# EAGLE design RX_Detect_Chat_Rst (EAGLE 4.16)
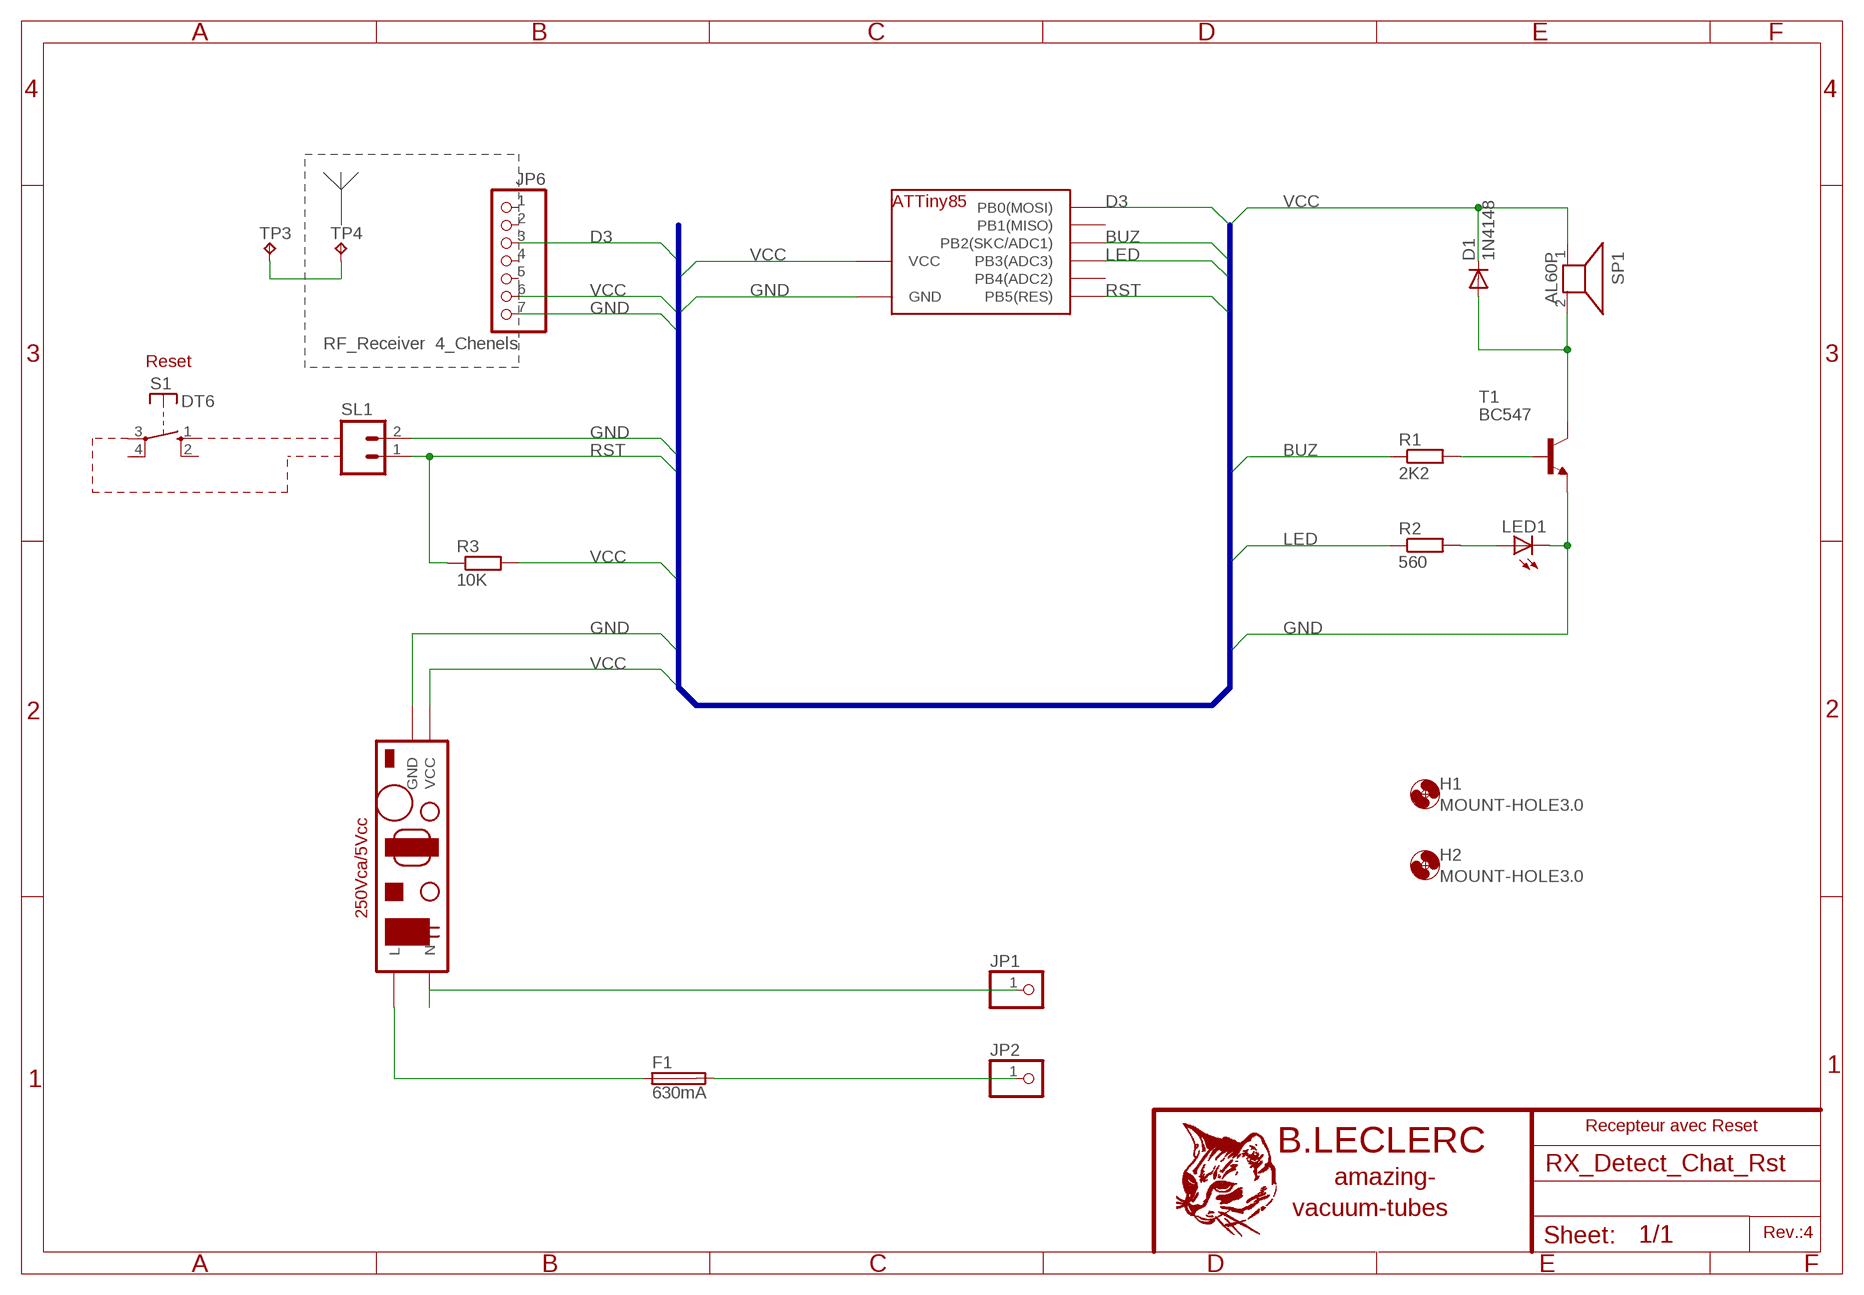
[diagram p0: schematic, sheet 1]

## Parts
D1  1N4148  DIODE-DO214BA  [DO214BA]
F1  630mA  FUSESHK20L  [SHK20L]
H1  MOUNT-HOLE3.0  [3,0]
H2  MOUNT-HOLE3.0  [3,0]
JP1  PINHD-1X1  [1X01]
JP2  PINHD-1X1  [1X01]
JP6  PINHD-1X7  [1X07]
LED1  LED5MM  [LED5MM]
R1  2K2  R-EU_M1206  [M1206]
R2  560  R-EU_M1206  [M1206]
R3  10K  R-EU_0207/10  [0207/10]
S1  DT6  [DT6]
SL1  M02  [02P]
SP1  AL60P  [AL60P]
T1  BC547  [TO92]
TP3  TPPAD1-20  [P1-20]
TP4  TPPAD1-20  [P1-20]
U$2  SWPWR250-5ALIM  [SWPWR250-5ALIM]
U$3  ATTINY85  [DIL08]

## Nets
BUZ: R1.1 U$3.7(PB2(SKC/ADC1))
D3: JP6.3 U$3.5(PB0(MOSI))
GND: JP6.7 LED1.K(C) SL1.2 T1.1(E) U$2.GND U$3.4(GND)
LED: R2.1 U$3.2(PB3(ADC3))
N$1: D1.A SP1.2 T1.3(C)
N$2: R1.2 T1.2(B)
N$3: LED1.A R2.2
N$4: JP1.1 U$2.N
N$5: F1.1A U$2.L
N$6: TP3.1(TP) TP4.1(TP)
N$7: F1.2A JP2.1
RST: R3.1 SL1.1 U$3.1(PB5(RES))
VCC: D1.C JP6.6 R3.2 SP1.1 U$2.VCC U$3.8(VCC)
Unconnected: JP6.1 JP6.2 JP6.4 JP6.5 S1.1(S) S1.2(S) S1.3(P) S1.4(P) U$3.3(PB4(ADC2)) U$3.6(PB1(MISO))

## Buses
B$1

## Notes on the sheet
- RF_Receiver  4_Chenels
- Reset
- Recepteur avec Reset
- Rev.:4

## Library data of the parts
D1 = diode:DIODE-: DIODE
F1 = fuse:FUSE: Fuse
H1 H2 = holes:MOUNT-HOLE: MOUNTING HOLE with drill center marker
JP1 JP2 = pinhead:PINHD-1X1: PIN HEADER
JP6 = pinhead:PINHD-1X7: PIN HEADER
LED1 = led:LED: LED
R1-R3 = rcl:R-EU_: RESISTOR, European symbol
S1 = switch-misc:DT: ITT SWITCH
SL1 = con-NANARD:M02: AMP QUICK CONNECTOR
SP1 = buzzer:AL60P: SPEAKER
T1 = transistor:BC547: NPN TRANSISTOR
TP3 TP4 = testpad:TP
U$2 = Arduino:SWPWR250-5ALIM
U$3 = atmel:ATTINY85

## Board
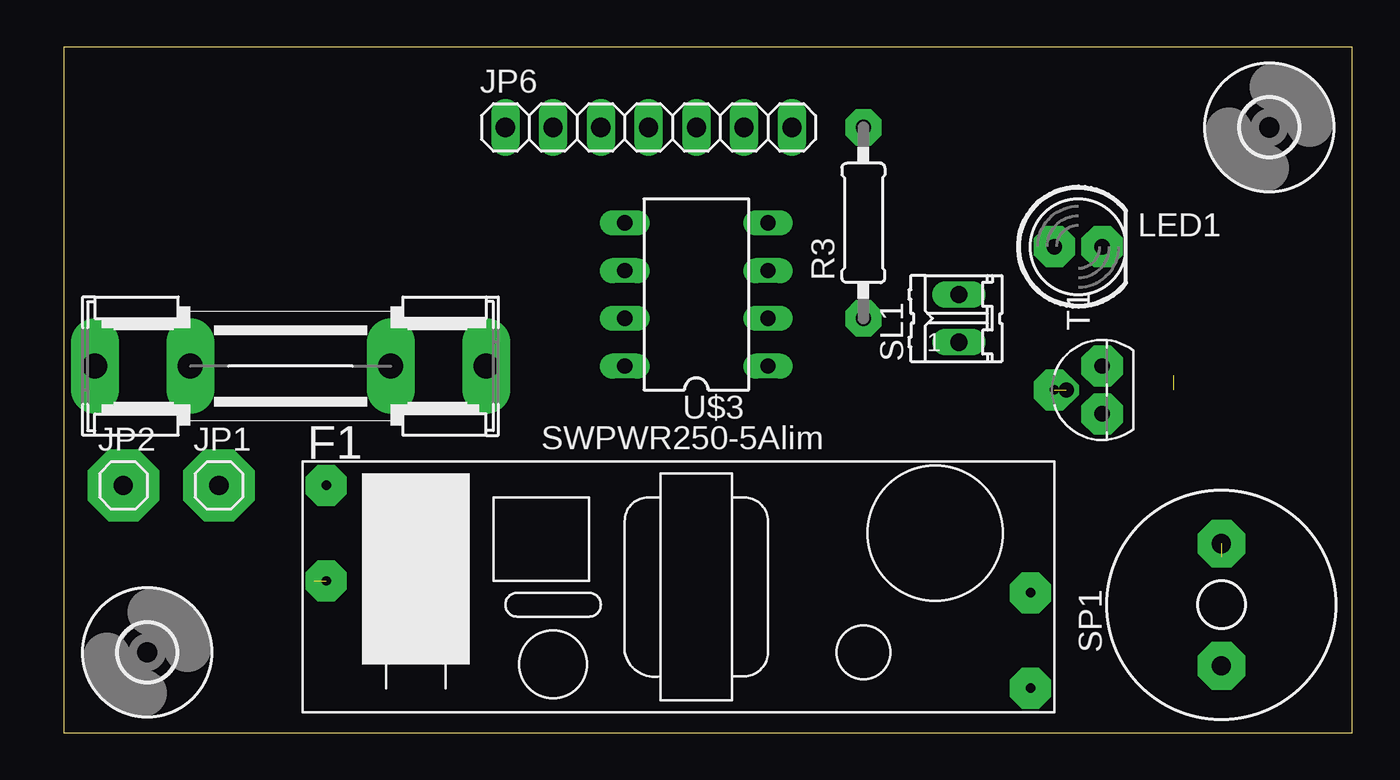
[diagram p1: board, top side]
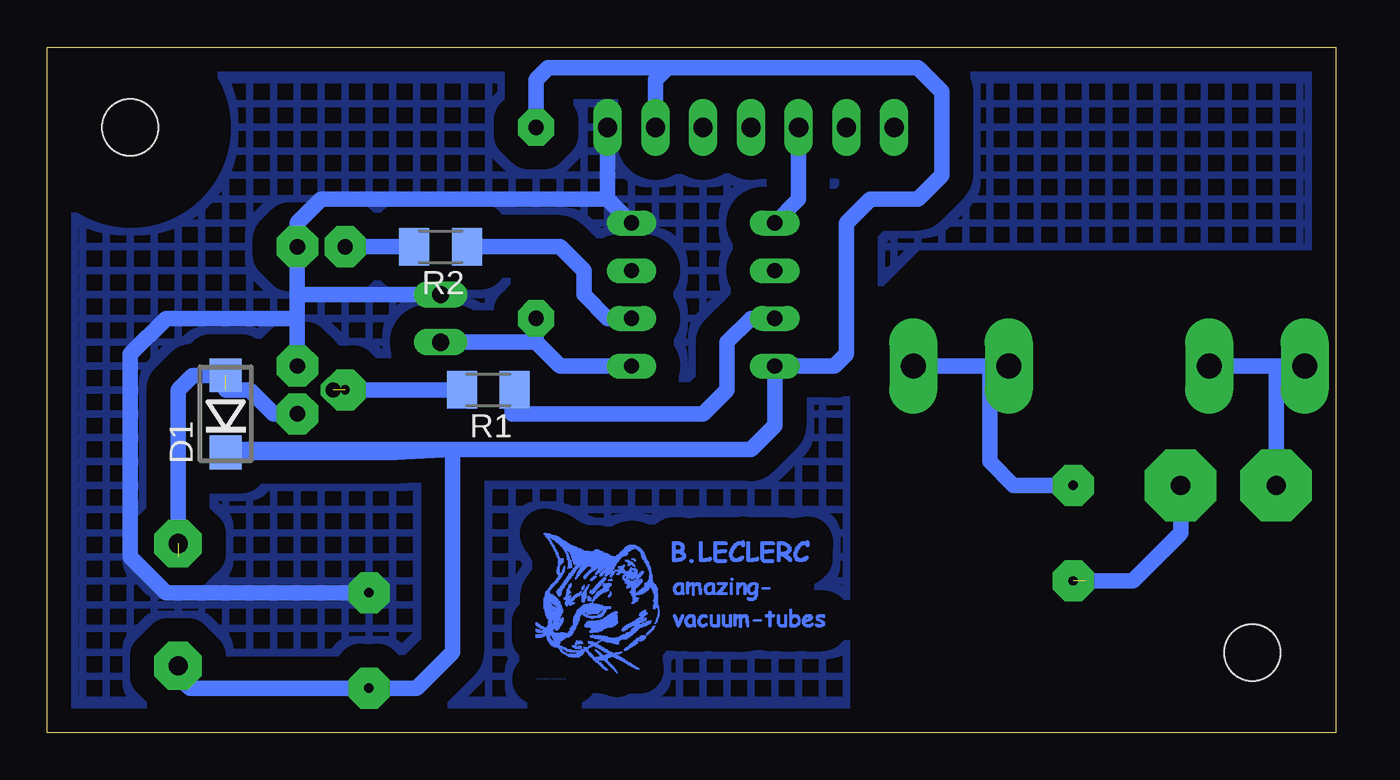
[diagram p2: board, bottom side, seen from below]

Size 68.56 x 36.5 mm. Coordinates in mm from the lower left corner, seen from the top.
Outline: 0,0 68.56,0 68.56,36.5 0,36.5 0,0
Copper layers (1*16): Top 0.035mm / dielectric 1.5mm / Bottom 0.035mm
Design rules "default": minimum track width 10mil, minimum drill 24mil, track to track 8mil, track to pad 8mil, pad to pad 8mil, via to via 8mil, smd to smd 8mil, copper to edge 40mil, drill to drill 8mil, minimum pad ring 10mil, minimum via ring 8mil, stop-mask expansion 4mil, vias tented up to drill 0mil, thermal gap 10mil

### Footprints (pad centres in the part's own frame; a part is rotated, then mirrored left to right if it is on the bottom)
DO214BA = smd 1.8 x 1.7: A 2.05,0; C -2.05,0
SHK20L = drill 1.321 pad 2.54 long: 1A -10.414,0; 1B -5.334,0; 2A 10.414,0; 2B 5.334,0
3,0 = hole 3: 0,0
1X01 = drill 1.016 octagon: 1 0,0
1X07 = drill 1.016 long: 1 -7.62,0; 2 -5.08,0; 3 -2.54,0; 4 0,0; 5 2.54,0; 6 5.08,0; 7 7.62,0
LED5MM = drill 0.813 octagon: A -1.27,0; K 1.27,0
M1206 = smd 1.6 x 2: 1 -1.4,0; 2 1.4,0
0207/10 = drill 0.813 octagon: 1 -5.08,0; 2 5.08,0
DT6 = drill 1.118 octagon: 1 -2.54,2.54; 2 2.54,2.54; 3 2.54,-2.54; 4 -2.54,-2.54
02P = drill 0.914 long: 1 -1.27,0; 2 1.27,0
AL60P = drill 1.016 pad 2.54 octagon: 1 -3.251,0; 2 3.251,0
TO92 = drill 0.813 octagon: 1 1.27,0; 2 0,1.905; 3 -1.27,0
P1-20 = drill 2.007 pad 3.15 octagon: 1 0,0
SWPWR250-5ALIM = drill 0.5 pad 2.184 octagon: GND 19.05,-0.635; L -18.415,5.08; N -18.415,0; VCC 19.05,-5.715
DIL08 = drill 0.813 long: 1 -3.81,-3.81; 2 -1.27,-3.81; 3 1.27,-3.81; 4 3.81,-3.81; 5 3.81,3.81; 6 1.27,3.81; 7 -1.27,3.81; 8 -3.81,3.81

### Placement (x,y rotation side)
D1  59.05,16.98 90 bottom
F1  12.06,19.52 180 top
H1  64.13,32.22 0 top
H2  4.44,4.28 0 top
JP1  8.25,13.17 0 top
JP2  3.17,13.17 0 top
JP6  31.11,32.22 0 top
LED1  53.97,25.87 0 top
R1  45.08,18.25 180 bottom
R2  47.62,25.87 180 bottom
R3  42.54,27.14 90 top
S1  not placed on the board
SL1  47.62,22.06 90 top
SP1  61.59,6.82 90 top
T1  55.24,18.25 90 top
TP3  not placed on the board
TP4  not placed on the board
U$2  32.38,8.09 0 top
U$3  33.65,23.33 90 top
U$5  [CHAT]  42.54,3.01 0 bottom

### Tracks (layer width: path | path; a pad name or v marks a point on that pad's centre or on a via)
BUZ
  Bottom 0.813: U$3.7 31.11,22.06 32.38,20.79 32.38,18.25 33.65,16.98 43.81,16.98 43.81,18.25 R1.1
D3
  Bottom 0.813: JP6.3 28.57,28.41 U$3.5
GND  (via drill 0.5)
  Bottom 0.813: 38.73,28.41 U$3.4 | 38.73,28.41 JP6.7 | 50.16,28.41 38.73,28.41 | 50.16,28.41 50.8,28.41 | U$2.GND 62.23,7.46 64.13,9.36 64.13,20.15 62.23,22.06 55.41,22.06 55.24,22.06 | 55.24,22.06 T1.1 | 50.16,28.41 53.97,28.41 55.24,27.14 LED1.K 55.24,23.33 | 55.24,22.06 55.24,23.33 | 55.24,23.33 SL1.2
  other vias: 38.73,32.22 37.46,27.14
  pour Bottom (isolate 1.27, no thermals, hatched): 0.63,25.87 22.22,25.87 26.03,22.06 26.03,0.47 67.94,0.47 67.94,36.03 0.63,36.03
LED
  Bottom 0.813: U$3.2 38.73,22.06 40,23.33 40,24.6 41.27,25.87 R2.1
N$1  (2 unrouted)
  Bottom 0.813: 59.05,19.52 D1.A 60.81,19.03 61.59,18.25 61.59,9.36 | T1.3 56.51,16.98 57.78,18.25 59.05,18.25
N$2  (1 unrouted)
  Bottom 0.813: R1.2 52.7,18.25
N$3
  Bottom 0.813: R2.2 LED1.A
N$4  (1 unrouted)
  Bottom 0.813: JP1.1 8.25,10.63 10.79,8.09 13.33,8.09 14.6,8.09
N$5
  Bottom 0.813: U$2.L 17.14,13.17 18.41,14.44 18.41,19.52 F1.1A
N$6  (1 unrouted)
N$7  (via drill 0.5 pad 1.78)
  Bottom 0.813: JP2.1 3.17,19.52 | 1.27,19.52 F1.2A 1.9,19.52 | 3.17,19.52 v6.98,19.52 6.98,18.88 6.34,19.52 1.9,19.52 | 3.17,19.52 1.9,19.52
N$8  (via drill 0.5)
  other vias: 23.49,32.22
N$9  (via drill 0.5)
  other vias: 26.03,32.22
N$10  (via drill 0.5)
  other vias: 28.57,32.22
N$11  (via drill 0.5)
  other vias: 31.11,32.22
N$12  (via drill 0.5)
  other vias: 33.65,32.22
N$13  (via drill 0.5)
  other vias: 36.19,32.22
N$14  (via drill 0.5 pad 2.18)
  other vias: 55.24,19.52
N$15  (via drill 0.5)
  other vias: 29.84,27.14
N$16  (via drill 0.5)
  other vias: 29.84,24.6
N$17  (via drill 0.5)
  other vias: 29.84,22.06
N$18  (via drill 0.5 pad 2.18)
  other vias: 55.24,16.98
N$19  (via drill 0.5)
  other vias: 37.46,22.06
N$20  (via drill 0.5)
  other vias: 29.84,19.52
N$21  (via drill 0.5)
  other vias: 37.46,24.6
N$22  (via drill 0.5)
  other vias: 37.46,19.52
N$23  (via drill 0.5 pad 2.18)
  other vias: 52.7,18.25
N$24  (via drill 0.5 pad 1.78)
  other vias: 6.98,19.52
N$25  (via drill 0.5 pad 1.78)
  other vias: 17.14,19.52
N$26  (via drill 0.5 pad 3.81)
  other vias: 3.17,13.17
N$27  (via drill 0.5 pad 3.81)
  other vias: 8.25,13.17
N$28  (via drill 0.5 pad 1.27)
  other vias: 61.59,3.64
N$29  (via drill 0.5 pad 1.27)
  other vias: 61.59,10
N$30  (via drill 0.5 pad 2.18)
  other vias: 52.7,25.87
N$31  (via drill 0.5 pad 2.18)
  other vias: 55.24,25.87
N$32  (via drill 0.5 pad 1.93)
  other vias: 42.54,32.22
N$33  (via drill 0.5 pad 1.93)
  other vias: 42.54,22.06
RST
  Bottom 0.813: 42.54,20.79 SL1.1 | 42.54,20.79 41.27,19.52 U$3.1 | 42.54,20.79 R3.1
VCC
  Bottom 0.813: 52.07,2.38 U$2.VCC | 52.07,2.38 60.96,2.38 61.59,3.01 SP1.1 61.59,3.64 | 46.98,15.08 31.11,15.08 29.84,16.34 U$3.8 26.66,19.52 26.03,20.15 26.03,27.14 24.76,28.41 22.22,28.41 20.95,29.68 20.95,34.12 22.22,35.39 35.55,35.39 | 46.98,15.08 59.05,15.08 D1.C 50.02,14.93 46.98,15.08 | 46.98,15.08 46.98,4.28 48.89,2.38 52.07,2.38 | JP6.6 36.19,34.76 35.55,35.39 | R3.2 42.54,34.76 41.91,35.39 35.55,35.39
